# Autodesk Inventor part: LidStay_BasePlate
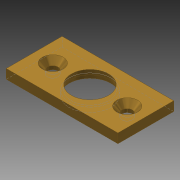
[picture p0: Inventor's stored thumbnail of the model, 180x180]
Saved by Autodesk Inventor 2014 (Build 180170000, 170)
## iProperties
Created: 2014-03
Part Number: LidStay_BasePlate
Material: Brass, Soft Yellow
Document SubType Name: Modeling
Designer: Beast
Density: 8.47 g/cm^3
Appearance: Brass - Satin
Author: Beast
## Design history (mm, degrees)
sketch "Sketch1"
  geometry: L1 (0, 0)-(38.1, 0); L2 (38.1, 0)-(38.1, -19.05); L3 (38.1, -19.05)-(0, -19.05); L4 (0, -19.05)-(0, 0); C1 r 6.35 at (19.05, -9.525); C2 r 1.786 at (6.35, -9.525); C3 r 1.786 at (31.75, -9.525); 3 further points
  constraints: 8 end point, 3 centre point, 3 coincident, 2 parallel, 1 horizontal, 1 perpendicular
  dimensions: "d0" = 38.1 distance of L2.end L3.end; "d1" = 19.05 distance of L2.end L1.end; "d2" = 6.35 distance from line of L4 point (6.35, -9.525); "d3" = 6.35 distance from line of L2 point (31.75, -9.525); "d6" = 12.7 diameter of C1; "d7" = 3.57187 diameter of C2; "d8" = 3.57187 diameter of C3
extrude "Extrusion1" new body sketch "Sketch1" distance "d9" = 3.175; taper "d10" = 0 deg
hole "Hole1" sketch "Sketch1" diameter "d11" = 12.7; stored, may be unused: countersink angle "d15" = 82 deg, drill point angle "d17" = 118 deg; dims "d12" = 19.05, "d13" = 14.2875, "d14" = 1.5875, "d16" = 25.4
hole "Hole2" diameter "d20" = 2.54; stored, may be unused: countersink angle "d24" = 82 deg, drill point angle "d26" = 118 deg; dims "d18" = 9.525, "d19" = 6.35, "d21" = 19.05, "d22" = 7.0866, "d23" = 1.5875, "d25" = 25.4
hole "Hole3" diameter "d29" = 2.54; stored, may be unused: countersink angle "d33" = 82 deg, drill point angle "d35" = 118 deg; dims "d27" = 9.525, "d28" = 6.35, "d30" = 19.05, "d31" = 7.0866, "d32" = 1.5875, "d34" = 25.4
body "Solid1"
